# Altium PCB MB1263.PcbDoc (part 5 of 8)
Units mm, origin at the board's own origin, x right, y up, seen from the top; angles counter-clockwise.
Board outline 86 x 120 mm, 6 copper layers (Top Layer, Signal Layer 1, Signal Layer 2, Signal Layer 3, Signal Layer 4, Bottom Layer), stack 1.556 mm thick; 392 components, 421 nets, 1978 pads, 1444 vias.
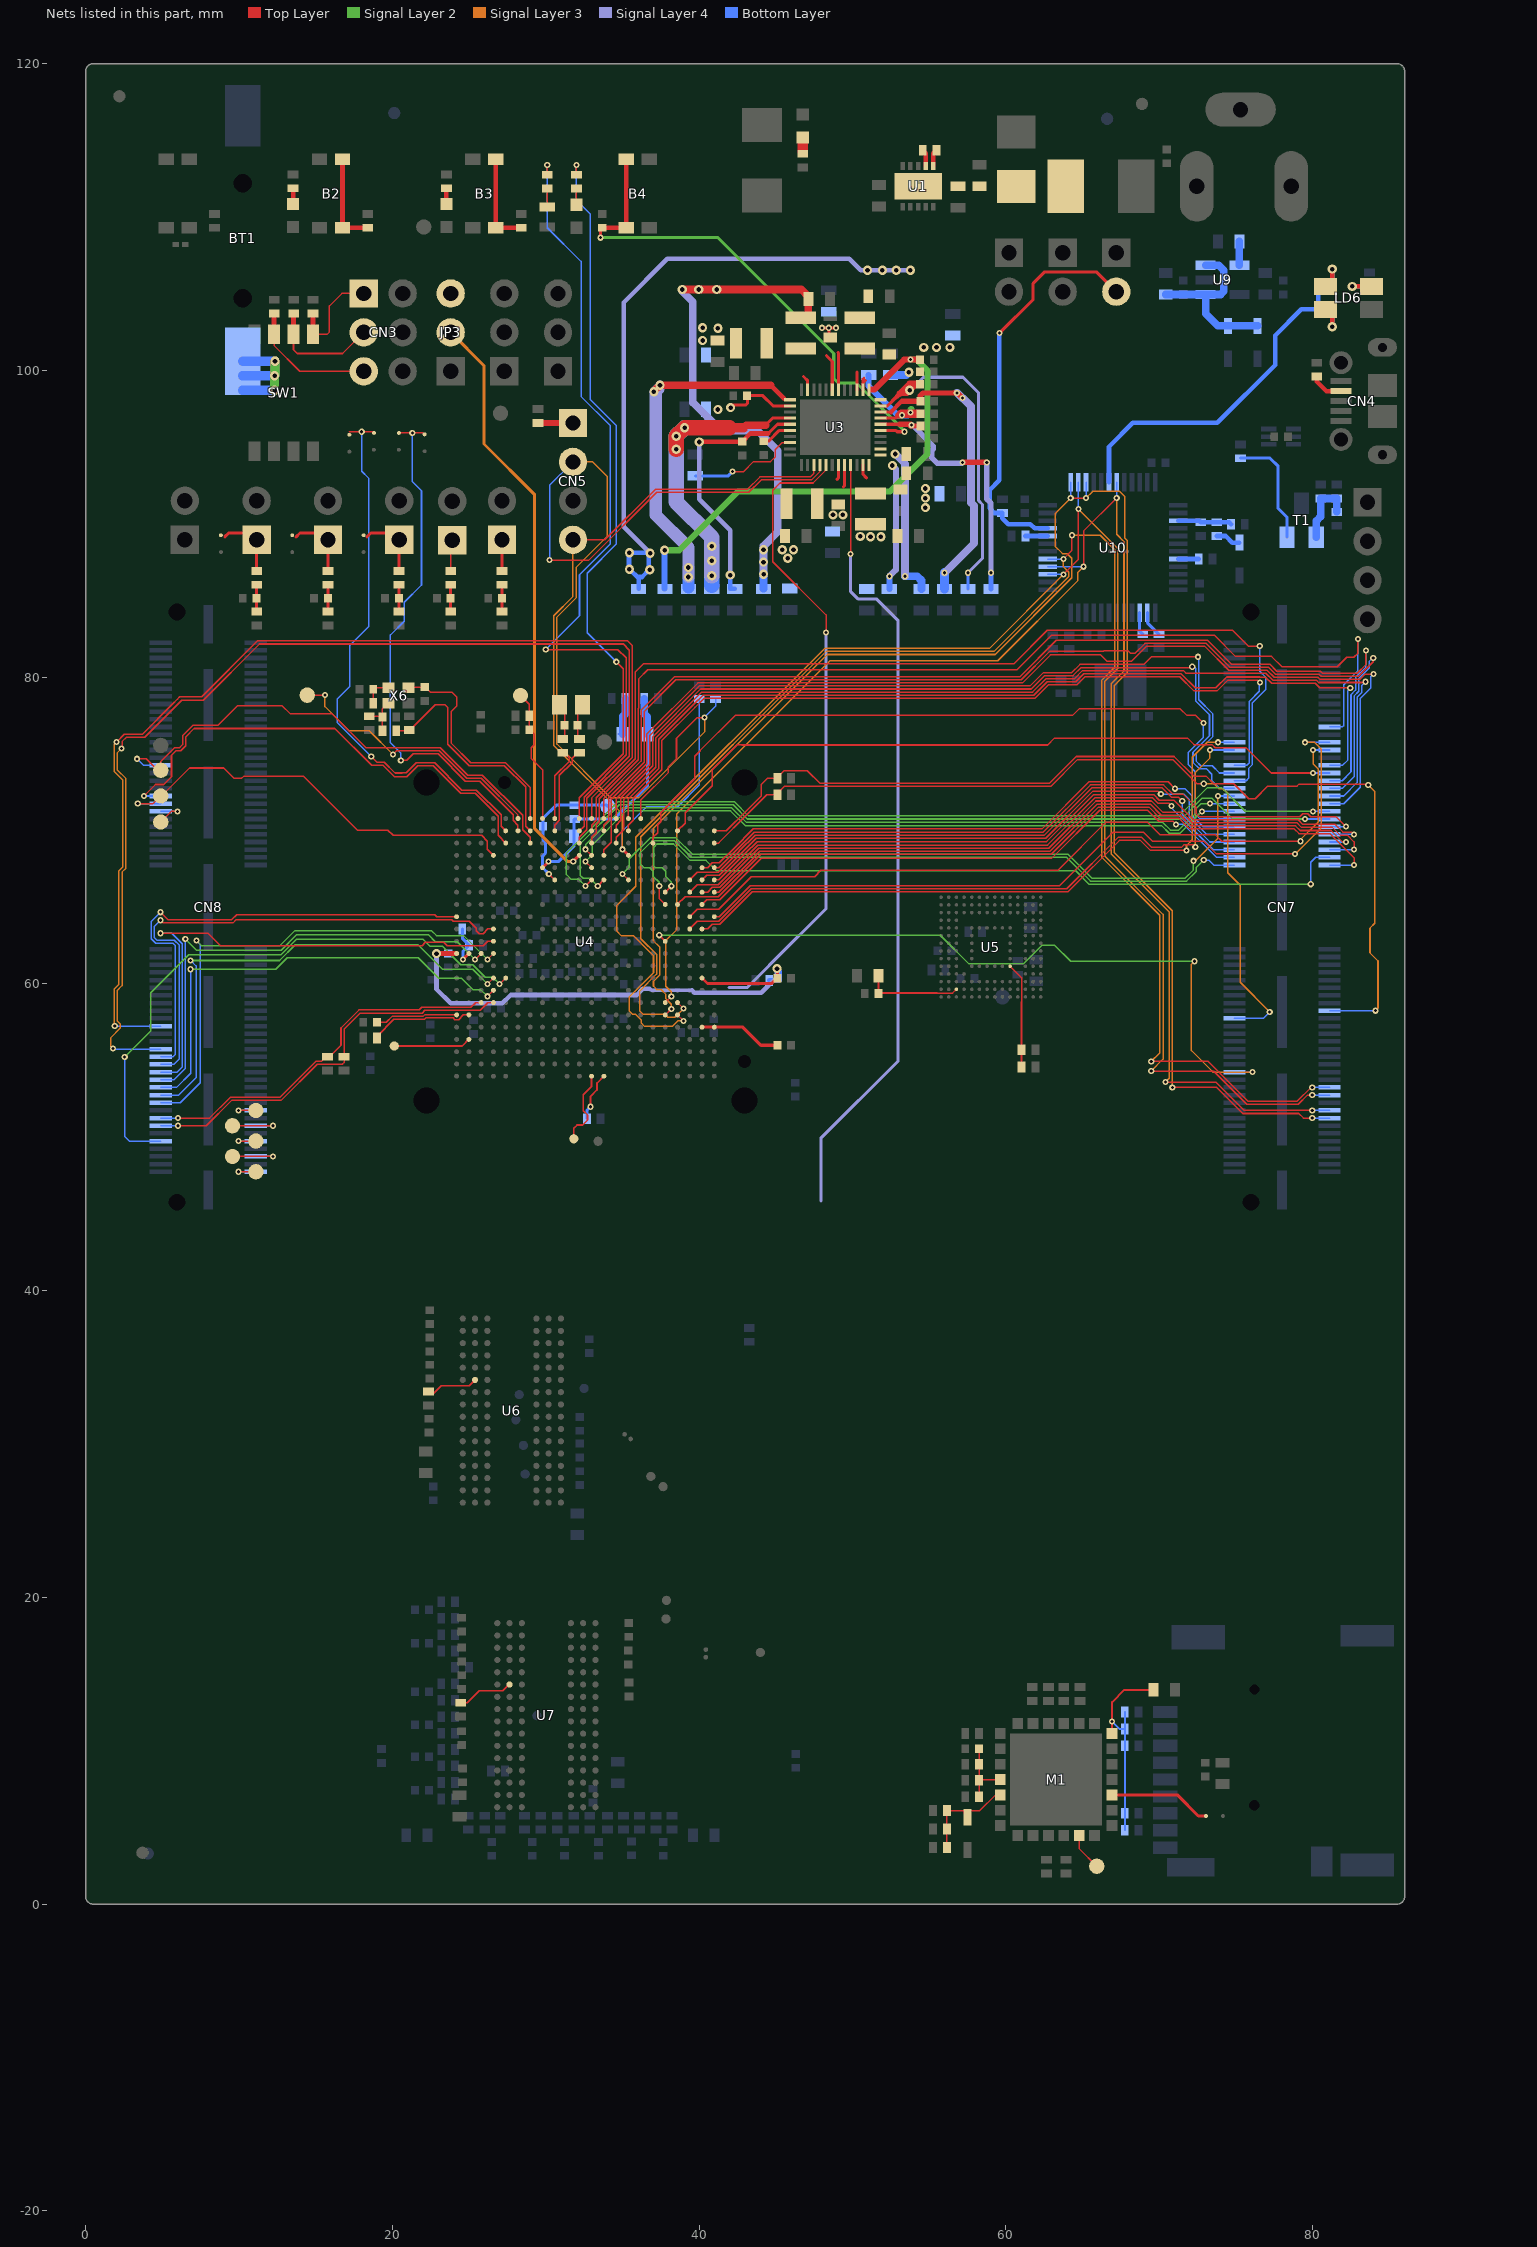
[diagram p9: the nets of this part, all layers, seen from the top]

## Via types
v1: diameter 0.4, hole 0.2, Top Layer to Bottom Layer, tented both sides, 771 vias
v2: diameter 0.6, hole 0.3, Top Layer to Bottom Layer, tented both sides, 670 vias
v3: diameter 0.4, hole 0.2, Top Layer to Bottom Layer, 3 vias

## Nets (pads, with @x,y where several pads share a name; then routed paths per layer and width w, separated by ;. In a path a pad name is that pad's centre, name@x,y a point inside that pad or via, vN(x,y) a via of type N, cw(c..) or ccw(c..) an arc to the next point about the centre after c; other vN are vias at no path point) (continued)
GPIO7: CN8.41 U4.V3 | length 32.1
  Top Layer w0.09: 20.934,73.5 21.646,74.212 22.681,74.212 24.469,72.425 25.396,72.425 26.895,70.926 26.895,69.675 U4.V3@27.39,69.18
  Top Layer w0.1: v1(3.8,72.25) 4.55,73 5.1,73 5.6,73.5 5.6,74.9 5.9,75.2 6.203,75.2 6.525,75.522 6.525,76.1 7.075,76.65 16.25,76.65 18.65,74.25 19.392,74.25 20.142,73.5 20.934,73.5
  Bottom Layer w0.1: v1(3.8,72.25) CN8.41@4.9,72.25
HDMI_CEC: CN7.93 U4.E11 | length 48.8
  Top Layer w0.1: v1@37.4,63.17 U4.E11@37.79,62.78
  Signal Layer 2 w0.1: v1(37.4,63.175) 55.72,63.175 57.595,61.3 61.125,61.3 62.35,62.525 63.175,62.525 64.225,61.475 v1(72.3,61.475)
  Signal Layer 3 w0.1: v1(72.3,61.475) 72.1,61.275 72.1,55.65 73.5,54.25 v1(76.075,54.25)
  Bottom Layer w0.1: CN7.93@74.9,54.25 v1(76.075,54.25)
HSE_IN: C33.2 U4.T1 X6.3 | length 14.9
  Top Layer w0.1: X6.3@21.05,79.3 21.1,79.35 C33.2@22.1,79.35 ; C33.2@22.1,79.3 22.2,79.3 22.5,79 23.9,79 24.2,78.7 24.2,78.125 23.85,77.775 23.85,75.676 25.106,74.42 27.381,74.42 28.99,72.811 U4.T1@28.99,70.78
HSE_OUT: R26.2 R303.1 U4.T2 | length 15.7
  Top Layer w0.09: 23.625,77.875 23.625,75.625 25.025,74.225 27.3,74.225 28.685,72.84 28.685,70.285 U4.T2@28.99,69.98
  Top Layer w0.1: R26.2@20.2,76.5 20.25,76.503 20.255,76.503 R303.1@21.1,76.5 ; R303.1@21.1,76.6 21.2,76.6 22.8,78.2 23.425,78.2 23.625,78 23.625,77.875
I2C2_SCL: CN7.79 R31.1 U4.A3 | length 54.6
  Top Layer w0.1: U4.A3@40.99,69.18 41.263,69.18 41.297,69.214 41.297,69.221 43.131,71.055 43.138,71.055 44.408,72.325 R31.1@45.1,72.325 45.1,72.425 45.55,72.875 62.925,72.875 64.675,74.625 70.886,74.625 72.461,73.05 v1(72.9,73.05)
  Signal Layer 3 w0.09: 74.15,72.725 74.45,72.425 74.45,67.25 75.27,66.43 75.27,65.4
  Signal Layer 3 w0.1: v1(72.9,73.05) 73.575,73.05 73.9,72.725 74.15,72.725 ; 75.275,65.4 75.275,60.1 v1(77.2,58.175)
  Bottom Layer w0.1: CN7.79@74.9,57.75 76.775,57.75 v1(77.2,58.175)
I2C2_SDA: CN7.78 R30.1 U4.A2 | length 65.7
  Top Layer w0.1: U4.A2@40.99,69.98 41.773,69.98 43.048,71.255 43.055,71.255 44.052,72.252 44.052,73.002 44.45,73.4 R30.1@45.1,73.4 45.1,73.475 45.525,73.9 47.05,73.9 47.875,73.075 62.842,73.075 64.592,74.825 70.969,74.825 72.244,73.55 73.05,73.55 73.55,73.05 74.855,73.05 75.83,72.075 76.25,72.075 77.075,72.9 78.98,72.9 79.105,73.025 83.625,73.025 v1(83.625,72.975)
  Signal Layer 3 w0.1: v1(83.625,72.975) 84.05,72.55 84.05,63.951 83.739,63.64 83.739,62.015 84.26,61.494 84.26,58.409 v1(84.104,58.253)
  Bottom Layer w0.1: CN7.78@81.1,58.25 84.101,58.25 v1(84.104,58.253)
I2C4_SCL: CN5.2 R53.2 U3.4 U4.G1 | length 72.8
  Top Layer w0.1: v1(30.251,87.629) 32.812,87.629 37.233,92.05 43.238,92.05 44.044,92.856 47.335,92.856 47.879,93.4 U3.4@47.879,93.836 ; U4.G1@36.19,70.78 36.19,71.982 37.995,73.787 37.995,74.17 38.525,74.7 38.525,76.02 39.855,77.35 40.323,77.35 v1(40.352,77.379)
  Signal Layer 3 w0.1: CN5.2@31.775,94.03 33.07,94.03 34,93.1 34,89.175 31.975,87.15 31.975,85.167 30.725,83.917 30.725,75.633 34.208,72.15 36.075,72.15 40.352,76.427 v1(40.352,77.379)
  Bottom Layer w0.1: v1(30.251,87.629) 30.251,92.506 CN5.2@31.775,94.03 ; v1(40.352,77.379) 41.075,78.102 R53.2@41.075,78.575
I2C4_SDA: CN5.4 R93.2 U3.3 U4.H4 | length 54.2
  Top Layer w0.1: CN5.4@31.775,88.95 33.85,88.95 37.15,92.25 43.155,92.25 43.961,93.056 47.252,93.056 47.479,93.283 U3.3@47.479,93.836
  Top Layer w0.2: v1@35,68.77 U4.H4@35.39,68.38
  Signal Layer 3 w0.1: CN5.4@31.775,88.95 31.775,85.25 30.525,84 30.525,75.55 35,71.075 v1(35,68.775)
  Bottom Layer w0.1: v1(35,68.775) 35,69.975 36.575,71.55 38.6,71.55 40,72.95 R93.2@40,78.575
I2C5_SCL: CN8.105 R34.1 U4.Y16 | length 24.7
  Top Layer w0.09: 21.75,58.3 21.925,58.475 25.116,58.475 25.421,58.78 U4.Y16@25.79,58.78
  Top Layer w0.1: v1(6.025,51.25) 8.084,51.25 9.434,52.6 12.662,52.6 15.017,54.955 15.38,54.955 15.675,55.25 R34.1@15.775,55.25 15.9,55.25 16.65,56 16.65,57.125 17.825,58.3 21.75,58.3
  Bottom Layer w0.1: CN8.105@4.9,51.25 v1(6.025,51.25)
I2C5_SDA: CN8.107 R35.1 U4.W16 | length 26.3
  Top Layer w0.09: 21.937,58.1 22.121,58.285 25.726,58.285 26.221,58.78 U4.W16@26.59,58.78
  Top Layer w0.1: v1(6.025,50.75) 7.867,50.75 9.517,52.4 12.745,52.4 15.1,54.755 16.73,54.755 16.85,54.875 R35.1@16.85,55.25 16.85,57.042 17.908,58.1 21.937,58.1
  Bottom Layer w0.1: CN8.107@4.9,50.75 v1(6.025,50.75)
JTCK_SWCLK: CN7.100 U4.D17 U10.15 U10.26 | length 113.8
  Top Layer w0.1: U4.D17@38.59,57.98 v1@38.98,57.59 ; v1(63.75,86.7) 64.725,87.675 v1(64.725,90.95) ; v1(69.475,54.325) 69.475,54.3 73.549,54.3 75.699,52.15 79.067,52.15 79.667,52.75 v1(79.975,52.75)
  Signal Layer 3 w0.1: v1(38.98,57.585) 38.601,57.585 38.246,57.23 36.445,57.23 36.24,57.435 36.24,57.625 35.835,58.03 35.645,58.03 35.44,58.235 35.44,59.141 37.025,60.726 37.025,61.842 35.737,63.13 34.945,63.13 34.625,63.45 34.625,65.115 35.875,66.365 35.875,69.556 48.194,81.875 58.925,81.875 v1(63.75,86.7) ; v1(64.725,90.95) 64.733,90.95 67.3,88.383 67.3,80.567 66.46,79.727 66.46,68.316 70.25,64.526 70.25,55.1 v1(69.475,54.325)
  Bottom Layer w0.1: U10.15@62.725,86.7 v1(63.75,86.7) ; v1(64.725,90.95) U10.26@64.725,92.7 ; v1(79.975,52.75) CN7.100@81.1,52.75
JTDI: CN7.98 U4.D16 U10.17 | length 106.8
  Top Layer w0.1: U4.D16@38.59,58.78 v1@38.98,58.39 ; v1(63.75,87.7) 64.3,88.25 v1(64.3,89.25) ; v1(69.475,54.95) 73.181,54.95 75.781,52.35 78.984,52.35 79.884,53.25 v1(79.975,53.25)
  Signal Layer 3 w0.1: v1(38.98,58.385) 38.978,58.385 38.413,57.82 37.957,57.82 37.747,58.03 36.32,58.03 36.14,58.21 36.14,59.558 37.225,60.643 37.225,61.925 36.2,62.95 36.2,69.599 48.276,81.675 59.22,81.675 64.1,86.555 64.1,86.845 63.75,87.195 v1(63.75,87.7) ; v1(64.3,89.25) 66.15,89.25 67.1,88.3 67.1,80.65 66.26,79.81 66.26,68.233 70.025,64.469 70.025,55.5 v1(69.475,54.95)
  Bottom Layer w0.1: U10.17@62.725,87.7 v1(63.75,87.7) ; v1(79.975,53.25) CN7.98@81.1,53.25
JTDO_TRACESWO: CN7.104 U4.E16 U10.16 U10.31 | length 106.9
  Top Layer w0.1: U4.E16@37.79,58.78 v1@38.179,59.17 ; v1(65.068,87.2) 65.068,89.518 v1(67.225,91.675) ; v1(70.4,53.6) 73.683,53.6 75.533,51.75 v1(79.975,51.75)
  Signal Layer 3 w0.1: v1(38.185,59.17) 38.185,59.484 37.826,59.843 37.826,62.824 38.55,63.547 38.55,71.1 48.525,81.075 59.468,81.075 64.7,86.307 64.7,86.832 v1(65.068,87.2) ; v1(67.225,91.675) 67.225,89.308 67.7,88.833 67.7,80.401 66.86,79.562 66.86,68.482 70.65,64.692 70.65,53.85 v1(70.4,53.6)
  Bottom Layer w0.1: U10.16@62.725,87.2 v1(65.068,87.2) ; v1(67.225,91.675) U10.31@67.225,92.7 ; v1(79.975,51.75) CN7.104@81.1,51.75
JTMS_SWDIO: CN7.106 U4.E17 U10.25 U10.27 | length 111.1
  Top Layer w0.1: U4.E17@37.79,57.98 v1@38.179,58.37 ; v1(64.225,91.675) v1(65.225,91.675) ; v1(70.85,53.25) 73.75,53.25 75.45,51.55 79.1,51.55 79.4,51.25 v1(79.975,51.25)
  Signal Layer 3 w0.1: v1(38.185,58.37) 38.185,58.675 37.835,59.025 37.835,59.314 37.524,59.625 37.255,59.625 37.025,59.855 37.025,60.16 37.425,60.56 37.425,60.824 37.426,60.825 37.426,62.4 37,62.826 37,70.116 48.359,81.475 59.303,81.475 64.3,86.472 64.3,87.75 64,88.05 63.687,88.05 63.687,88.063 63.225,88.525 63.225,90.675 v1(64.225,91.675) ; v1(65.225,91.675) 65.675,92.125 67.4,92.125 67.75,91.775 67.75,89.075 67.9,88.925 67.9,80.29 67.06,79.45 67.06,68.565 70.85,64.775 v1(70.85,53.25)
  Bottom Layer w0.1: v1(64.225,91.675) U10.25@64.225,92.7 ; v1(65.225,91.675) U10.27@65.225,92.7 ; v1(79.975,51.25) CN7.106@81.1,51.25
LCD_BL_CTRL: CN8.111 U4.V14 | length 38.5
  Top Layer w0.1: v1@27,59.99 U4.V14@27.39,60.38
  Signal Layer 2 w0.1: v1(2.55,55.225) 4.25,56.925 4.25,59.42 6.73,61.9 12.741,61.9 13.766,62.925 21.975,62.925 22.45,62.45 23.265,62.45 24.465,61.25 25.24,61.25 26.05,60.44 26.545,60.44 v1(26.995,59.99)
  Bottom Layer w0.1: v1(2.55,55.225) 2.55,50.05 2.85,49.75 CN8.111@4.9,49.75
LED_B: R5.1 U4.M2 | length 53.7
  Top Layer w0.09: v1(30,81.8) 34.7,81.8 35.25,81.25 35.25,74.938 32.495,72.183 32.495,70.285 U4.M2@32.19,69.98
  Top Layer w0.1: R5.1@30.1,112.75 v1(30.1,113.4)
  Bottom Layer w0.1: v1(30,81.8) 32.2,84 32.2,86.68 34.2,88.68 34.2,96.4 32.3,98.3 32.3,107.1 30.1,109.3 v1(30.1,113.4)
LED_STLINK: R57.2 R58.2 U10.30 | length 22.3
  Bottom Layer w0.3: U10.30@66.725,92.7 66.725,95.025 68.275,96.575 73.775,96.575 77.55,100.35 77.55,102.275 79.25,103.975 R58.2@80.375,103.975 R57.2@80.375,105.475
LED_Y: R6.1 U4.M1 | length 47.3
  Top Layer w0.09: U4.M1@32.19,70.78 32.19,72.146 35.05,75.007 35.05,80.55
  Top Layer w0.1: R6.1@32,112.75 v1(32,113.4) ; v1(34.6,81) 35.05,80.55
  Bottom Layer w0.1: v1(32,113.4) 32,111.1 32.9,110.2 32.9,98.1 34.6,96.4 34.6,88.675 32.7,86.775 32.7,82.9 v1(34.6,81)
LTDC_B0: CN7.57 U4.B8 | length 38.5
  Top Layer w0.09: U4.B8@40.19,65.18 40.495,65.485 41.336,65.485 44.052,68.2
  Top Layer w0.1: 44.052,68.2 63,68.2 66.125,71.325 69.241,71.325 69.967,70.599 70.901,70.599 v1(71.1,70.4)
  Bottom Layer w0.1: v1(71.1,70.4) 71.586,70.4 73.736,68.25 CN7.57@74.9,68.25
LTDC_B1: CN7.54 U4.A7 | length 45.7
  Top Layer w0.09: U4.A7@40.99,65.98 41.294,65.98 43.582,68.267 43.582,68.274 43.957,68.65 46.839,68.65
  Top Layer w0.1: 46.839,68.65 62.88,68.65 65.955,71.725 69.407,71.725 70.133,70.999 71.366,70.999 72.064,70.3 78.889,70.3 79.189,70 81.203,70 81.953,69.25 v1(82.175,69.25)
  Bottom Layer w0.1: CN7.54@81.1,69.25 v1(82.175,69.25)
LTDC_B2: CN7.56 U4.B7 | length 48.2
  Top Layer w0.09: U4.B7@40.19,65.98 40.558,65.98 40.863,66.285 41.33,66.285 43.392,68.346 43.392,68.353 43.889,68.85 46.756,68.85
  Top Layer w0.1: 46.756,68.85 62.797,68.85 65.872,71.925 69.489,71.925 70.216,71.199 71.449,71.199 72.147,70.5 78.972,70.5 79.272,70.2 81.286,70.2 81.786,69.7 82.255,69.7 82.7,69.255 v1(82.7,68.75)
  Bottom Layer w0.1: CN7.56@81.1,68.75 v1(82.7,68.75)
LTDC_B3: CN7.55 U4.C7 | length 39.5
  Top Layer w0.09: U4.C7@39.39,65.98 39.885,66.475 41.252,66.475 43.202,68.425 43.202,68.432 43.82,69.05 46.666,69.05
  Top Layer w0.1: 46.666,69.05 62.714,69.05 65.789,72.125 69.572,72.125 69.922,71.775 70.625,71.775 70.8,71.6 v1(70.803,71.603)
  Signal Layer 2 w0.1: v1@70.8,71.607 v1(70.803,71.603)
  Bottom Layer w0.1: v1(70.803,71.603) 70.803,71.465 73.519,68.75 CN7.55@74.9,68.75
LTDC_B4: CN7.51 U4.B6 | length 38.9
  Top Layer w0.09: U4.B6@40.19,66.78 40.495,67.085 41.324,67.085 42.822,68.582 42.822,68.589 43.732,69.5 46.558,69.5
  Top Layer w0.1: 46.558,69.5 62.599,69.5 65.649,72.55 69.925,72.55 v1(70.1,72.375)
  Bottom Layer w0.1: v1(70.1,72.375) 71.6,72.375 71.95,72.025 71.95,70.884 73.084,69.75 CN7.51@74.9,69.75
LTDC_B5: CN7.52 U4.A6 | length 46.7
  Top Layer w0.09: U4.A6@40.99,66.78 41.288,66.78 43.012,68.503 43.012,68.511 43.776,69.275 46.616,69.275
  Top Layer w0.1: 46.616,69.275 62.656,69.275 65.706,72.325 69.655,72.325 70.005,71.975 70.955,71.975 72.23,70.7 79.055,70.7 79.355,70.4 81.475,70.4 81.975,69.9 82.55,69.9 v1(82.7,69.75)
  Bottom Layer w0.1: CN7.52@81.1,69.75 v1(82.7,69.75)
LTDC_B6: CN7.53 U4.C6 | length 40
  Top Layer w0.09: U4.C6@39.39,66.78 39.885,67.275 41.246,67.275 42.632,68.661 42.632,68.668 43.664,69.7 46.475,69.7
  Top Layer w0.1: 46.475,69.7 62.516,69.7 65.591,72.775 70.201,72.775 70.801,72.175 71.25,72.175 v1(71.5,71.925)
  Bottom Layer w0.1: v1(71.5,71.925) 71.5,71.051 73.301,69.25 CN7.53@74.9,69.25
LTDC_B7: CN7.50 U4.A5 | length 46
  Top Layer w0.09: U4.A5@40.99,67.58 41.282,67.58 42.442,68.74 42.442,68.747 43.595,69.9 46.9,69.9
  Top Layer w0.1: 46.9,69.9 62.433,69.9 65.508,72.975 70.283,72.975 70.883,72.375 71.545,72.375 72.425,71.495 72.425,71.105 72.63,70.9 79.155,70.9 79.355,71.1 79.68,71.1 79.88,70.9 81.525,70.9 v1(82.175,70.25)
  Bottom Layer w0.1: CN7.50@81.1,70.25 v1(82.175,70.25)
LTDC_CLK: CN7.36 U4.D2 | length 47
  Top Layer w0.09: U4.D2@38.59,69.98 39.085,70.475 39.085,71.143 40.845,72.904 40.845,73.943 40.854,73.952 ; 41.45,74.555 41.457,74.555 42.476,75.575 42.775,75.575
  Top Layer w0.1: 40.85,73.956 41.45,74.555 ; 42.775,75.575 62.725,75.575 63.175,76.025 71.836,76.025 72.261,75.6 73.445,75.6 73.645,75.4 75.65,75.4 77.3,73.75 v1(80.025,73.75)
  Bottom Layer w0.1: v1(80.025,73.75) CN7.36@81.1,73.75
LTDC_DE: CN7.49 U4.B5 | length 39
  Top Layer w0.09: U4.B5@40.19,67.58 40.558,67.58 40.863,67.885 41.318,67.885 42.252,68.818 42.252,68.825 43.526,70.1 46.9,70.1
  Top Layer w0.1: 46.9,70.1 62.35,70.1 65.425,73.175 70.578,73.175 v1(71.028,72.725)
  Bottom Layer w0.1: v1(71.028,72.725) 71.675,72.725 72.15,72.25 72.15,70.967 72.867,70.25 CN7.49@74.9,70.25
LTDC_G0: CN7.43 U4.L4 | length 45.6
  Top Layer w0.1: v1@32.6,68.77 U4.L4@32.99,68.38
  Signal Layer 2 w0.1: v1(32.6,68.775) 32.6,69.075 35,71.475 42.134,71.475 43.084,70.525 70.233,70.525 70.733,70.025 71.267,70.025 72.425,71.183 72.425,71.45 72.725,71.75 v1(73.3,71.75)
  Bottom Layer w0.1: v1(73.3,71.75) CN7.43@74.9,71.75
LTDC_G1: CN7.41 U4.H6 | length 47
  Top Layer w0.1: v1@35,67.17 U4.H6@35.39,66.78
  Signal Layer 2 w0.1: v1(35,67.175) 35.45,67.625 35.45,68.16 36.81,69.52 38.496,69.52 39.566,68.45 64.041,68.45 65.591,66.9 71.7,66.9 72.225,67.425 v1(72.225,68.025)
  Signal Layer 3 w0.1: v1(72.225,68.025) 72.355,68.025 73.825,69.495 v1(73.825,72.25)
  Bottom Layer w0.1: v1(73.825,72.25) CN7.41@74.9,72.25
LTDC_G2: CN7.37 U4.L2 | length 64
  Top Layer w0.09: U4.L2@32.99,69.98 32.99,70.348 33.295,70.653 33.295,72.148 35.83,74.684 35.83,78.034 35.833,78.036 35.835,78.038
  Top Layer w0.1: 35.835,78.038 35.835,80.335 36.375,80.875 60.525,80.875 62.7,83.05 74.775,83.05 75.8,82.025 v1(76.55,82.025)
  Bottom Layer w0.1: CN7.37@74.9,73.25 75.675,73.25 75.825,73.4 75.825,74.05 76.075,74.3 76.075,78.325 76.929,79.179 76.929,80.001 76.55,80.38 v1(76.55,82.025)
LTDC_G3: CN7.42 U4.J3 | length 65.6
  Top Layer w0.09: U4.J3@34.59,69.18 34.59,69.548 35.085,70.043 35.085,72.043 37.17,74.129 37.17,76.027
  Top Layer w0.1: 37.175,76.027 40.173,79.025 61.739,79.025 62.614,79.9 64.466,79.9 64.991,80.425 71.575,80.425 71.75,80.25 76.948,80.25 77.408,79.79 80.249,79.79 80.389,79.65 83.4,79.65 v1(83.45,79.7) ; v1(83.45,79.7) 83.575,79.7 v1(83.45,79.7)
  Bottom Layer w0.1: CN7.42@81.1,72.25 82.025,72.25 82.9,73.125 82.9,78.689 83.2,78.989 83.2,79.45 v1(83.45,79.7)
LTDC_G4: CN7.48 U4.K6 | length 55.5
  Top Layer w0.12: v1(33.39,66.38) U4.K6@33.79,66.78
  Signal Layer 2 w0.1: v1(33.39,66.38) 32.89,66.88 32.445,66.88 32.24,67.085 32.24,69.125 34.79,71.675 42.217,71.675 43.142,70.75 71.442,70.75 72.792,72.1 73.445,72.1 74.795,70.75 v1(79.5,70.75)
  Bottom Layer w0.1: v1(79.5,70.75) CN7.48@81.1,70.75
LTDC_G5: CN7.60 U4.D8 | length 50.2
  Top Layer w0.09: U4.D8@38.59,65.18 39.085,65.675 41.258,65.675 43.772,68.189 43.772,68.196 44.026,68.45 45.85,68.45
  Top Layer w0.1: 45.85,68.45 62.963,68.45 66.038,71.525 69.324,71.525 70.05,70.799 71.283,70.799 71.982,70.1 78.807,70.1 79.107,69.8 79.272,69.8 81.12,69.8 82.7,68.22 v1(82.7,67.75)
  Bottom Layer w0.1: CN7.60@81.1,67.75 v1(82.7,67.75)
LTDC_G6: CN7.58 U4.E7 | length 50.6
  Top Layer w0.1: U4.E7@37.79,65.98 v1@38.179,66.37
  Signal Layer 2 w0.1: v1(38.185,66.37) 38.185,66.64 37.825,67 37.825,67.35 37.6,67.575 37.15,67.575 37.035,67.69 37.035,68.914 37.24,69.12 38.33,69.12 39.4,68.05 40.45,68.05 41.125,67.375 64.55,67.375 65.425,66.5 v1(79.875,66.5)
  Bottom Layer w0.1: v1(79.875,66.5) 79.875,67.925 80.2,68.25 CN7.58@81.1,68.25
LTDC_G7: CN7.59 U4.E8 | length 45.3
  Top Layer w0.1: v1(37.4,66.375) 37.4,65.57 U4.E8@37.79,65.18
  Signal Layer 2 w0.1: v1(37.4,66.375) 37.4,66.625 37,67.025 37,67.35 36.775,67.575 36.4,67.575 36.175,67.8 36.175,68.575 36.919,69.32 38.413,69.32 39.483,68.25 63.958,68.25 65.508,66.7 71.783,66.7 72.425,67.342 72.425,67.6 v1(72.9,68.075)
  Bottom Layer w0.1: v1(72.9,68.075) 73.225,68.075 73.55,67.75 CN7.59@74.9,67.75
LTDC_HSYNC: CN7.33 U4.H2 | length 54.9
  Top Layer w0.09: U4.H2@35.39,69.98 35.39,70.348 35.695,70.653 35.695,72.102 37.56,73.967 37.56,75.275
  Top Layer w0.1: 37.56,75.275 37.56,75.57 37.565,75.575 37.565,75.865 39.725,78.025 39.739,78.025 40.339,78.625 61.905,78.625 62.78,79.5 64.633,79.5 65.158,80.025 71.342,80.025 72.267,79.1 73.769,79.1 74.478,79.809 76.424,79.809 v1(76.579,79.654)
  Bottom Layer w0.1: CN7.33@74.9,74.25 75.7,74.25 75.875,74.425 75.875,78.425 76.525,79.075 76.525,79.654 76.525,79.675 76.558,79.675 v1(76.579,79.654)
LTDC_R0: CN7.47 U4.F3 | length 50.8
  Top Layer w0.09: U4.F3@36.99,69.18 36.99,69.548 37.295,69.853 37.295,70.385 37.485,70.575 37.485,71.156 39.705,73.376 39.705,74.855 40.064,75.214
  Top Layer w0.1: 40.064,75.214 42.35,77.5 64.35,77.5 64.775,77.925 71.375,77.925 71.8,77.5 72.375,77.5 v1(72.875,77)
  Bottom Layer w0.1: v1(72.875,77) 72.875,76.083 71.9,75.108 71.9,74.284 72.35,73.834 72.35,71.05 72.65,70.75 CN7.47@74.9,70.75
LTDC_R1: CN7.39 U4.J2 | length 55.1
  Top Layer w0.09: U4.J2@34.59,69.98 34.59,70.348 34.895,70.653 34.895,72.122 36.98,74.207 36.98,76.119
  Top Layer w0.1: 36.985,76.119 40.091,79.225 61.656,79.225 62.531,80.1 64.383,80.1 64.908,80.625 72.1,80.625 v1(72.15,80.675)
  Bottom Layer w0.1: v1(72.15,80.675) 72.2,80.725 72.375,80.55 72.375,78.442 73.275,77.542 73.275,76.183 72.2,75.108 72.2,74.442 72.617,74.025 73.075,74.025 73.425,73.675 73.425,73.255 73.93,72.75 CN7.39@74.9,72.75
LTDC_R2: CN7.46 U4.L6 | length 56.4
  Top Layer w0.12: v1(32.59,66.38) U4.L6@32.99,66.78
  Signal Layer 2 w0.1: v1(32.59,66.38) 32.14,66.83 31.645,66.83 31.35,67.125 31.35,68.518 34.707,71.875 42.3,71.875 43.225,70.95 71.295,70.95 73.145,72.8 74.053,72.8 75.603,71.25 v1(80.025,71.25)
  Bottom Layer w0.1: v1(80.025,71.25) CN7.46@81.1,71.25
LTDC_R3: CN7.44 U4.K4 | length 70.4
  Top Layer w0.09: U4.K4@33.79,68.38 33.79,68.748 34.285,69.243 34.285,72.049 36.6,74.365 36.6,76.305
  Top Layer w0.1: 36.605,76.305 39.925,79.625 61.08,79.625 62.905,81.45 66.18,81.45 66.605,81.025 68.178,81.025 69.153,82 72.975,82 74.525,80.45 77.031,80.45 77.491,79.99 80.332,79.99 80.472,79.85 83.075,79.85 83.425,80.2 v1(83.975,80.2)
  Bottom Layer w0.1: CN7.44@81.1,71.75 82.025,71.75 83.1,72.825 83.1,78.607 83.8,79.307 83.8,80.05 83.95,80.2 v1(83.975,80.2)
LTDC_R4: CN7.35 U4.J1 | length 54.7
  Top Layer w0.09: U4.J1@34.59,70.78 34.59,72.086 36.79,74.286 36.79,76.212
  Top Layer w0.1: 36.795,76.212 40.008,79.425 61.574,79.425 62.449,80.3 64.3,80.3 64.825,80.825 68.995,80.825 69.495,81.325 v1(72.525,81.325)
  Bottom Layer w0.1: v1(72.525,81.325) 72.575,81.275 72.575,78.525 73.475,77.625 73.475,76.1 72.4,75.025 72.4,74.525 72.7,74.225 73.45,74.225 73.925,73.75 CN7.35@74.9,73.75
LTDC_R5: CN7.40 U4.K2 | length 70.1
  Top Layer w0.09: U4.K2@33.79,69.98 33.79,70.348 34.095,70.653 34.095,72.128 36.41,74.443 36.41,77.475
  Top Layer w0.1: 36.415,77.475 36.415,77.765 38.475,79.825 60.997,79.825 62.847,81.675 66.35,81.675 66.4,81.725 67.955,81.725 68.13,81.55 68.42,81.55 69.07,82.2 73.058,82.2 74.608,80.65 77.114,80.65 77.574,80.19 80.414,80.19 80.554,80.05 82.992,80.05 83.95,81.008 v1(83.95,81.25)
  Bottom Layer w0.1: CN7.40@81.1,72.75 81.95,72.75 82.7,73.5 82.7,78.772 83,79.072 83,79.91 83.675,80.585 83.675,81.025 83.925,81.275 v1(83.95,81.25)
LTDC_R6: CN7.38 U4.K1 | length 69.2
  Top Layer w0.1: U4.K1@33.79,70.78 33.79,72.099 36.215,74.524 36.215,77.848 38.392,80.025 60.914,80.025 63.289,82.4 73.141,82.4 74.691,80.85 77.197,80.85 77.657,80.39 80.497,80.39 80.637,80.25 82.909,80.25 83.475,80.816 v1(83.475,81.725)
  Bottom Layer w0.1: CN7.38@81.1,73.25 81.925,73.25 82.5,73.825 82.5,78.855 82.8,79.155 82.8,79.993 83.475,80.668 v1(83.475,81.725)
LTDC_R7: CN7.45 U4.L5 | length 45.8
  Top Layer w0.1: v1@32.6,67.97 U4.L5@32.99,67.58
  Signal Layer 2 w0.1: v1(32.6,67.975) 33.04,68.415 33.04,69.075 35.24,71.275 42.051,71.275 43.001,70.325 70.15,70.325 70.65,69.825 71.35,69.825 v1(72.775,71.25)
  Bottom Layer w0.1: v1(72.775,71.25) CN7.45@74.9,71.25
LTDC_VSYNC: CN7.34 U4.H1 | length 59.9
  Top Layer w0.09: 37.365,74.45 37.365,75.941 39.649,78.225 39.656,78.225 ; 76.525,80.009 76.535,79.999 76.924,79.999 77.328,79.595 80.168,79.595 80.463,79.3 v1(82.45,79.3)
  Top Layer w0.1: U4.H1@35.39,70.78 35.39,72.073 37.365,74.048 37.365,74.45 ; 39.656,78.225 40.256,78.825 61.822,78.825 62.697,79.7 64.549,79.7 65.074,80.225 65.075,80.225 71.425,80.225 72.35,79.3 73.686,79.3 74.395,80.009 76.525,80.009
  Bottom Layer w0.1: CN7.34@81.1,74.25 81.95,74.25 82.3,74.6 82.3,79.125 82.45,79.275 v1(82.45,79.3)
MCO1: CN8.33 TP7.1 U4.T3 | length 34.4
  Top Layer w0.09: 18.7,75.4 23.134,75.4 24.929,73.605 25.872,73.605 28.495,70.982 28.495,70.043 28.99,69.548 U4.T3@28.99,69.18
  Top Layer w0.1: v1(3.35,74.675) 3.95,74.675 TP7.1@4.7,73.925 ; TP7.1@4.9,73.925 4.9,74.5 5.8,75.4 6.12,75.4 6.325,75.605 6.325,76.183 6.992,76.85 8.616,76.85 9.891,78.125 12.825,78.125 13.35,77.6 16.081,77.6 18.281,75.4 18.7,75.4
  Bottom Layer w0.1: v1(3.35,74.675) 3.775,74.25 CN8.33@4.9,74.25
MCO2: CN8.43 TP8.1 U4.W4 | length 28.4
  Top Layer w0.09: 19.45,70.025 19.7,70.025 20.05,69.675 25.826,69.675 26.2,69.301 26.2,68.77 U4.W4@26.59,68.38
  Top Layer w0.1: v1(3.4,71.75) 4.4,71.75 TP8.1@4.9,72.25 4.95,72.25 6.775,74.075 9,74.075 9.675,73.4 10.17,73.4 10.32,73.55 14.192,73.55 17.717,70.025 19.45,70.025
  Bottom Layer w0.1: v1(3.4,71.75) CN8.43@4.9,71.75
NAND_ALE: CN8.101 U4.W12 | length 33.3
  Top Layer w0.1: v1@26.2,61.59 U4.W12@26.59,61.98
  Signal Layer 2 w0.1: v1(7.225,62.825) 7.55,62.5 12.675,62.5 13.625,63.45 22.575,63.45 22.875,63.15 24.634,63.15 v1(26.195,61.59)
  Bottom Layer w0.1: CN8.101@4.9,52.25 6.175,52.25 7.475,53.55 7.475,62.575 v1(7.225,62.825)
NAND_CLE: CN8.89 U4.AB9 | length 31.6
  Top Layer w0.1: v1(4.875,64.675) 5.372,64.178 9.52,64.178 9.85,64.508 22.766,64.508 22.894,64.38 U4.AB9@24.19,64.38
  Bottom Layer w0.1: v1(4.875,64.675) 4.275,64.075 4.275,62.95 4.575,62.65 5.7,62.65 5.85,62.5 5.85,55.4 5.7,55.25 CN8.89@4.9,55.25
NAND_D0: CN8.87 U4.M3 | length 74
  Top Layer w0.09: U4.M3@32.19,69.18 32.19,69.548 32.685,70.043 32.685,72.09 35.44,74.845 35.44,80.41 35.44,81.76 35.04,82.16
  Top Layer w0.1: v1(2.35,75.354) 2.375,75.379 2.375,75.797 2.658,76.08 3.855,76.08 6.274,78.499 7.674,78.499 11.335,82.16 35.04,82.16
  Signal Layer 2 w0.1: v1@2.329,75.375 v1(2.35,75.354)
  Signal Layer 3 w0.1: v1(1.775,55.778) 1.625,55.928 1.625,56.48 2.25,57.105 2.25,57.395 2.075,57.57 2.075,59.592 2.375,59.892 2.375,67.292 2.625,67.542 2.625,73.383 2.075,73.933 2.075,75.079 v1(2.35,75.354)
  Bottom Layer w0.1: v1@1.728,55.778 v1(1.775,55.778) ; v1@1.775,55.75 CN8.87@4.9,55.75
NAND_D1: CN8.81 U4.L1 | length 70.9
  Top Layer w0.1: v1(2.025,75.779) 2.526,76.28 3.705,76.28 5.65,78.225 6,78.575 6,78.582 6.143,78.725 7.575,78.725 11.215,82.365 35.335,82.365 35.635,82.065 35.635,74.764 32.99,72.119 U4.L1@32.99,70.78
  Signal Layer 3 w0.1: v1(1.9,57.25) 1.875,57.25 1.875,59.675 2.175,59.975 2.175,67.375 2.425,67.625 2.425,73.3 1.875,73.85 1.875,75.629 v1(2.025,75.779)
  Bottom Layer w0.1: v1(1.9,57.25) CN8.81@4.9,57.25
NAND_D2: CN7.29 U4.C10 | length 44.2
  Top Layer w0.09: U4.C10@39.39,63.58 39.885,64.075 40.316,64.075 40.863,64.075 ; 40.863,64.075 41.27,64.075 43.395,66.2 44.425,66.2
  Top Layer w0.1: 44.425,66.2 63.967,66.2 67.317,69.55 68.858,69.55 69.508,68.9 71.445,68.9 71.62,69.075 72.2,69.075 v1(72.35,68.925)
  Signal Layer 3 w0.1: v1(72.35,68.925) 72.35,73.775 73.3,74.725 v1(73.3,75.25)
  Bottom Layer w0.1: v1(73.3,75.25) CN7.29@74.9,75.25
NAND_D3: CN7.27 U4.B10 | length 43.6
  Top Layer w0.09: U4.B10@40.19,63.58 40.558,63.58 40.863,63.885 41.349,63.885 43.464,66 44.335,66
  Top Layer w0.1: 44.335,66 64.05,66 67.4,69.35 68.775,69.35 69.425,68.7 v1(71.775,68.7)
  Signal Layer 3 w0.1: v1(71.775,68.7) 71.775,69.025 72.15,69.4 72.15,74.775 73.125,75.75 v1(73.825,75.75)
  Bottom Layer w0.1: v1(73.825,75.75) CN7.27@74.9,75.75
NAND_D4: CN8.91 U4.W10 | length 34.4
  Top Layer w0.09: 23.875,64.18 23.98,64.075 25.025,64.075 25.485,63.615 25.485,63.453 25.663,63.275 25.916,63.275 26.221,63.58 U4.W10@26.59,63.58
  Top Layer w0.1: v1(4.875,64.15) 5.047,63.978 9.603,63.978 9.805,64.18 23.875,64.18
  Bottom Layer w0.1: v1(4.875,64.15) 4.475,63.75 4.475,63.033 4.658,62.85 5.783,62.85 6.1,62.533 6.1,55.1 5.75,54.75 CN8.91@4.9,54.75
NAND_D5: CN8.95 U4.Y12 | length 31.2
  Top Layer w0.1: v1@25.4,61.59 U4.Y12@25.79,61.98
  Signal Layer 2 w0.1: v1(6.5,62.925) 7.225,62.2 12.758,62.2 13.758,63.2 22.35,63.2 22.8,62.75 24.235,62.75 v1(25.395,61.59)
  Bottom Layer w0.1: CN8.95@4.9,53.75 5.758,53.75 6.5,54.492 v1(6.5,62.925)
NAND_D6: CN8.93 U4.W11 | length 33.6
  Top Layer w0.09: 12.175,62.5 21.95,62.5 22.15,62.7 23.35,62.7 23.575,62.475 25.916,62.475 26.221,62.78 U4.W11@26.59,62.78
  Top Layer w0.1: v1(4.875,63.3) 7.975,63.3 8.775,62.5 12.175,62.5
  Bottom Layer w0.1: v1(4.875,63.3) 5.616,63.3 6.3,62.616 6.3,54.575 5.975,54.25 CN8.93@4.9,54.25
NAND_D7: CN8.99 U4.W14 | length 31.9
  Top Layer w0.1: v1@26.2,59.99 U4.W14@26.59,60.38
  Signal Layer 2 w0.1: v1(6.85,61.525) 12.649,61.525 13.674,62.55 21.664,62.55 23.264,60.95 25.235,60.95 v1(26.195,59.99)
  Bottom Layer w0.1: CN8.99@4.9,52.75 6.075,52.75 7.2,53.875 7.2,61.175 v1(6.85,61.525)
NAND_NCE: CN8.97 U4.W15 | length 30.4
  Top Layer w0.1: v1@6.803,60.953 v1(6.85,60.953) ; v1@26.2,59.19 U4.W15@26.59,59.58
  Signal Layer 2 w0.1: v1(6.85,60.953) 12.403,60.953 13.15,61.7 21.692,61.7 23.022,60.37 24.505,60.37 25.245,59.63 25.755,59.63 v1(26.195,59.19)
  Bottom Layer w0.1: CN8.97@4.9,53.25 5.925,53.25 6.85,54.175 v1(6.85,60.953)
NAND_NOE: CN7.30 U4.C9 | length 50.6
  Top Layer w0.09: U4.C9@39.39,64.38 39.885,64.875 40.316,64.875 40.863,64.875 ; 40.863,64.875 41.264,64.875 43.389,67 47.525,67 47.925,67.4
  Top Layer w0.1: 47.925,67.4 63.375,67.4 66.5,70.525 69.25,70.525 70.065,69.71 73.665,69.71 74.075,69.3 v1(79.2,69.3)
  Signal Layer 3 w0.1: v1(79.2,69.3) 79.15,69.35 80.375,70.575 80.375,74 80.025,74.35 v1(80.025,75.25)
  Bottom Layer w0.1: v1(80.025,75.25) CN7.30@81.1,75.25
NAND_NWAIT: CN7.24 U4.L3 | length 69.2
  Top Layer w0.09: U4.L3@32.99,69.18 32.99,69.548 33.295,69.853 33.295,70.385 33.485,70.575 33.485,72.07 36.02,74.605 36.02,77.941
  Top Layer w0.1: 36.025,77.941 36.025,77.946 36.049,77.969 36.049,79.874 36.65,80.475 60.725,80.475 62.975,82.725 73.6,82.725 74.975,81.35 77.325,81.35 78,80.675 81.6,80.675 82.225,81.3 82.686,81.3 82.95,81.564 v1(82.95,82.475)
  Bottom Layer w0.1: CN7.24@81.1,76.75 81.95,76.75 82.025,76.825 82.025,79.501 82.95,80.426 v1(82.95,82.475)
NAND_NWE: CN7.28 U4.A9 | length 51.1
  Top Layer w0.09: U4.A9@40.99,64.38 41.306,64.38 43.326,66.4 46.936,66.4
  Top Layer w0.1: 46.936,66.4 63.5,66.4 67,69.9 68.95,69.9 69.54,69.31 72.9,69.31 73.735,68.475 v1(78.85,68.475)
  Signal Layer 3 w0.1: v1(78.85,68.475) 78.87,68.475 80.575,70.18 80.575,75.3 80.125,75.75 v1(79.5,75.75)
  Bottom Layer w0.1: v1(79.5,75.75) CN7.28@81.1,75.75
NetB2_3: B2.3 B2.4 R9.1 | length 6.1
  Top Layer w0.3: B2.4@16.75,113.75 B2.3@16.75,109.3 R9.1@18.4,109.3
NetB3_3: B3.3 B3.4 R10.1 | length 6.1
  Top Layer w0.3: B3.4@26.75,113.75 B3.3@26.75,109.3 R10.1@28.4,109.3
NetB4_3: B4.3 B4.4 C5.2 U3.17 | length 34.5
  Top Layer w0.2: v1(33.575,108.65) 33.575,109.2 C5.2@33.675,109.3 ; U3.17@51.829,96.086 52.814,96.086 52.9,96 v1(53.4,96) ; v1@53.375,96.075 v1@53.4,96.1
  Top Layer w0.3: C5.2@33.675,109.3 B4.4@35.25,109.3 ; B4.3@35.25,113.75 B4.4@35.25,109.3 ; B4.4@35.35,109.2 B4.4@35.25,109.3
  Signal Layer 2 w0.2: v1(33.575,108.65) 41.225,108.65 48.775,101.1 48.775,99.475 49.075,99.175 50.258,99.175 53.4,96.033 v1(53.4,96)
NetBT1_1: BT1.1 JP3.3 | length 13.9
  Signal Layer 2 w0.6: v2(12.325,98.7) v2(12.325,99.65) 12.35,99.675 v2(12.35,100.6)
  Signal Layer 3 w0.6: v2(12.325,98.7) v2(12.325,99.65) 12.35,99.675 v2(12.35,100.6)
  Signal Layer 4 w0.6: v2(12.325,98.7) v2(12.325,99.65) 12.35,99.675 v2(12.35,100.6)
  Bottom Layer w0.6: BT1.1@10.225,98.7 10.25,98.7 v2(12.325,98.7) v2(12.325,99.65) ; BT1.1@10.225,99.65 10.25,99.65 v2(12.325,99.65) ; BT1.1@10.25,100.6 v2(12.35,100.6) 12.35,99.675 v2(12.325,99.65)
NetC3_2: C3.2 D1.2 F1.2 R7.1 U1.EP
NetC6_2: C6.2 L1.2 R82.1 | length 33.7
  Top Layer w0.5: v2(38.9,105.275) v2(39.975,105.275) v2(41.15,105.275) 46.65,105.275 C6.2@47.1,104.825 ; L1.2@47.1,103.275 47.125,103.3 47.125,103.425 C6.2@47.125,104.65
  Signal Layer 4 w0.5: v2@38.9,105.15 39.575,104.475 39.575,97.908 41.427,96.056 43.819,96.056 45.125,94.75 45.125,89.475 44.2,88.55 v2(44.2,88.3) v2(44.2,87.5) 44.202,87.498 v2(44.202,86.706) ; v2(38.9,105.275) 38.9,105.152 v2@38.902,105.15
  Bottom Layer w0.5: R82.1@44.202,85.756 v2(44.202,86.706)
NetC7_2: C7.2 L2.2 R87.1 | length 43.2
  Signal Layer 4 w0.3: v2@36.775,88.1 35.075,89.8 35.075,104.425 37.925,107.275 49.775,107.275 50.525,106.525 50.95,106.525 50.956,106.531 v2(50.977,106.531) v2(51.952,106.531) v2(52.852,106.531) v2(53.777,106.531)
  Bottom Layer w0.3: 36.025,86.525 36.275,86.525 36.75,87 36.725,87.025 36.725,88.075 36.7,88.1 35.452,88.1 35.425,88.1 35.425,87.075 35.46,87.04 36.052,86.448 R87.1@36.052,85.75
  other v2: 36.777,87.006 35.452,87.031 36.802,88.081 35.452,88.106
NetC8_2: C8.2 L3.1 R59.2
  other v2: 40.225,101.95 41.225,102.75 40.225,102.775
NetC9_2: C9.2 R50.2 U3.28 | length 3.9
  Top Layer w0.2: v1(48,102.775) v1@48.425,102.775 ; v1(48.45,102.775) 48.475,102.75 C9.2@48.475,102.25 ; v1@48.45,102.8 48.462,102.788 48.475,102.775 v1(48.925,102.775) ; 49.05,101.175 49.079,101.146 U3.28@49.079,98.736
NetC10_2: C10.2 R60.2 U3.24 | length 1.5
  Top Layer w0.2: 50.754,99.504 50.725,99.475 50.675,99.425 50.675,98.74 U3.24@50.679,98.736 50.679,99.179 50.85,99.35
  other v2: 54.65,101.5 55.475,101.5 56.35,101.5
NetC11_2: C11.2 R86.1 U3.23 | length 33.1
  Top Layer w0.4: 51.2,98.75 51.425,98.75 53.375,100.7 v1(53.775,100.7) C11.2@54.4,100.7
  Signal Layer 2 w0.4: v2(37.75,88.275) 38.7,88.275 42.525,92.1 52.425,92.1 54.9,94.575 54.9,99.975 54.175,100.7 v1(53.775,100.7)
  Bottom Layer w0.3: R86.1@37.75,85.783 R86.1@37.777,85.756
  Bottom Layer w0.4: R86.1@37.75,85.783 v2(37.75,88.275)
NetC13_2: C13.2 R76.1 U3.21 | length 23.7
  Top Layer w0.2: U3.21@51.829,97.686 52.286,97.686 52.65,98.05
  Top Layer w0.25: 52.65,98.05 52.875,98.275
  Top Layer w0.3: 52.875,98.275 53.075,98.475 v2@53.55,98.475 ; v2(53.725,98.7) 54,98.975 ; v2@53.825,98.75 53.75,98.675 v2@53.55,98.475 ; 54.1,99 53.763,98.663 53.575,98.475 v2@53.55,98.475
  Top Layer w0.4: 53.075,98.475 53.512,98.912 53.725,99.125 C13.2@54.4,99.125
  Signal Layer 4 w0.2: v2(53.725,98.7) 53.775,98.7 54.625,99.55 57.2,99.55 58.225,98.525 58.225,91.506 58.475,91.256 58.475,87.75 57.529,86.804 v1@57.525,86.8
  Bottom Layer w0.2: R76.1@57.527,85.756 v1(57.527,86.806)
NetC14_2: C14.2 R63.2 U3.36 | length 4.8
  Top Layer w0.2: v2(42.05,97.575) 42.225,97.75 43.05,97.75 43.15,97.85 43.15,98.356 43.15,98.375 44.125,98.375 44.814,97.686 U3.36@45.929,97.686
  other v2: 41.225,97.45
NetC15_2: C15.2 R77.1 U3.20 | length 20.3
  Top Layer w0.2: U3.20@51.829,97.286 52.507,97.286
  Top Layer w0.3: 52.507,97.286 53.227,98.006
  Top Layer w0.35: 53.25,97.975 C15.2@54.425,97.975 54.425,98.35 54.6,98.525 v1(56.8,98.525) 56.85,98.525 v1(57.175,98.2)
  Signal Layer 4 w0.5: v1@56,86.8 56.004,86.804 57.925,88.725 57.925,91.169 57.725,91.369 57.725,97.65 v1(57.175,98.2) 57.15,98.2 56.813,98.538 v1@56.8,98.55
  Bottom Layer w0.6: R77.1@56.002,85.756 v1(56.002,86.806)
NetC16_2: C16.2 R62.2 U3.19 | length 8.8
  Top Layer w0.2: U3.19@51.829,96.886 52.786,96.886 52.956,97.056 53,97.1
  Top Layer w0.4: v1@53.225,97.233 v1@53.225,97.1 ; v1(53.775,97.25) 53.225,97.25 53.15,97.25 53.1,97.2 52.956,97.056 53.225,97.056 v1(53.225,97.075) v1@53.225,97.1 ; C16.2@54.225,97.1 53.775,97.1 v1@53.225,97.1
  Top Layer w0.5: v1@53.771,97.2 53.775,97.2 C16.2@54.375,97.2
  Signal Layer 2 w0.4: v1(53.775,97.25) 53.775,97.429 53.827,97.481
  Bottom Layer w0.4: R62.2@51.05,99.7 51.05,98.975 52.95,97.075 v1(53.225,97.075) 53.6,97.075 v1(53.775,97.25)
NetC17_2: C17.2 R75.1 U3.18 | length 17.6
  Top Layer w0.2: U3.18@51.829,96.486 53.085,96.486
  Top Layer w0.35: 53.085,96.486 53.789,96.486 v1(53.85,96.425) ; v1@53.775,96.375 53.8,96.375 v1(53.85,96.425) ; C17.2@54.425,96.375 53.9,96.375 v1(53.85,96.425) ; v1(57.175,94) v1(58.75,94)
  Signal Layer 4 w0.35: v1(53.85,96.425) 53.908,96.425 55.283,95.05 55.283,94.871 55.175,94.763 55.175,94.287 55.512,93.95 57.125,93.95 v1(57.175,94) ; v1(58.75,94) 58.75,93.975 58.75,91.625 59.025,91.35 59.025,86.808 v1(59.027,86.806)
  Bottom Layer w0.35: R75.1@59.027,85.756 v1(59.027,86.806)
NetC20_1: C20.1 U3.40 | length 2
  Top Layer w0.2: C20.1@44.202,95.381 44.527,95.381 45.232,96.086 U3.40@45.929,96.086
NetC21_2: C21.2 R83.1 U3.39 | length 17.1
  Top Layer w0.2: 44.507,95.886 45.107,96.486 U3.39@45.929,96.486
  Top Layer w0.3: v2(40.002,95.331) 40.027,95.356 C21.2@42.802,95.356 43.332,95.886 44.507,95.886
  Signal Layer 4 w0.3: v2(40.002,95.331) 40.002,91.598 42.025,89.575 v2(42.025,86.65)
  Bottom Layer w0.3: v2(42.025,86.65) 42.025,85.756 R83.1@42.327,85.756
NetC22_2: C22.2 R78.1 U3.14 | length 10.1
  Signal Layer 4 w0.2: v2(52.775,94.55) v2@52.775,94.625
  Signal Layer 4 w0.5: v2(52.775,94.55) 53.425,93.9 v1(53.425,86.575)
  Bottom Layer w0.5: v1(53.425,86.575) 54.225,86.575 54.5,86.3 R78.1@54.5,85.75
NetC23_2: C23.2 R79.2 U3.13 | length 8.3
  Signal Layer 4 w0.4: v1(52.4,86.575) 52.825,87 52.825,93.575 v2(52.6,93.8)
  Bottom Layer w0.4: R79.2@52.4,85.75 v1(52.4,86.575)
NetC24_2: C24.2 R68.2 U3.12
  other v2: 54.75,91.05 54.75,91.675 54.75,92.3
NetC25_2: C25.2 R72.2 U3.8 | length 1.5
  Top Layer w0.2: 49.4,92.4 49.479,92.479 U3.8@49.479,93.836
  other v2: 48.725,90.575 49.375,90.575
NetC26_2: C26.2 L4.2 R80.1
  other v2: 51.175,89.15 51.85,89.15 50.5,89.175
NetC27_2: C27.2 L5.2 R81.1
  other v2: 45.775,87.75 45.425,88.3 46.15,88.3
NetC28_2: C28.2 R16.1 R21.2 | length 1.8
  Top Layer w0.2: R21.2@11.15,84.275 C28.2@11.15,85.15 R16.1@11.15,86.025
NetC29_2: C29.2 R17.1 R22.2 | length 1.8
  Top Layer w0.2: R22.2@15.8,84.275 C29.2@15.8,85.15 R17.1@15.8,86.025
NetC30_2: C30.2 R18.1 R23.2 | length 1.8
  Top Layer w0.2: R23.2@20.425,84.275 C30.2@20.425,85.15 R18.1@20.425,86.025
NetC31_2: C31.2 R19.1 R24.2 | length 1.8
  Top Layer w0.2: R24.2@23.8,84.27 C31.2@23.8,85.145 R19.1@23.8,86.02
NetC32_2: C32.2 R20.1 R25.2 | length 1.8
  Top Layer w0.2: R25.2@27.15,84.27 C32.2@27.15,85.145 R20.1@27.15,86.02
NetC35_2: C35.2 R26.1 R302.2 X6.1 | length 2.5
  Top Layer w0.1: R302.2@18.5,77.45 19.25,77.45 19.325,77.375 19.4,77.3 19.35,77.25 R26.1@19.35,76.5 ; C35.2@19.35,77.4 19.35,77.95 X6.1@19.5,78.1
NetC36_1: C36.1 R28.2 X2.1 | length 2.4
  Top Layer w0.1: X2.1@30.9,78.2 31.225,77.875 C36.1@31.225,76.85 31.225,76.1 R28.2@31.1,75.975
NetC37_2: C37.2 R29.2 X2.2 | length 2.4
  Top Layer w0.1: R29.2@32.2,75.975 32.075,76.1 C37.2@32.075,76.85 32.075,77.875 X2.2@32.4,78.2
NetC38_2: C38.2 R27.1 TP4.1 U4.R1 | length 8.8
  Top Layer w0.1: TP4.1@28.35,78.8 28.925,78.225 R27.1@28.925,77.475 C38.2@28.925,76.575 29.245,76.255 29.245,75.589 29.053,75.397 29.053,74.692 29.119,74.625 29.79,73.955 U4.R1@29.79,70.78
NetC39_1: C39.1 C41.2 U5.C2 | length 6.3
  Top Layer w0.09: 55.5,59.4 56.382,59.4
  Top Layer w0.1: 56.382,59.4 56.525,59.4 U5.C2@56.775,59.65
  Top Layer w0.13: C39.1@51.7,60.525 C41.2@51.7,59.375 51.725,59.4 55.5,59.4
NetC40_2: C40.2 C93.2 R101.2 U4.AB12 U4.B14 | length 35.9
  Top Layer w0.2: U4.B14@40.19,60.38 40.55,60.02 44.745,60.02 C40.2@45.1,60.375 45.1,60.975 v2(45.075,61)
  Top Layer w0.3: v2(22.875,61.975) 22.88,61.98 U4.AB12@24.19,61.98
  Signal Layer 4 w0.2: 36.761,59.675 36.852,59.585 39.529,59.585 39.534,59.58
  Signal Layer 4 w0.3: v2@22.95,62.05 v2(22.875,61.975) 22.875,59.65 23.795,58.73 27.171,58.73 27.716,59.275 35.925,59.275 36.325,59.675 36.761,59.675 ; 39.534,59.58 39.689,59.425 44.05,59.425 45.075,60.45 v2(45.075,61)
  Bottom Layer w0.3: v2(22.875,61.975) 22.88,61.98 C93.2@23.65,61.98 ; R101.2@44.575,60.225 45.25,60.225 45.25,60.825 v2(45.075,61)
NetC42_1: C42.1 U4.AB17 | length 5.4
  Top Layer w0.1: C42.1@19,57.5 19.6,57.5 20,57.9 22.019,57.9 22.099,57.98 U4.AB17@24.19,57.98
NetC43_2: C43.2 U4.A18 U4.B18 | length 5.4
  Top Layer w0.2: U4.B18@40.19,57.18 U4.A18@40.99,57.18 42.845,57.18 44.025,56 C43.2@45.1,56
NetC55_2: C55.2 M1.20 R111.2 R113.2 R115.2 R121.2 R135.2 | length 13.8
  Top Layer w0.13: M1.20@66.925,11.125 v3(66.925,11.9) 66.925,13.175 67.725,13.975 C55.2@69.625,13.975
  Bottom Layer w0.13: v3(66.925,11.9) 67.4,11.425 R113.2@67.75,11.425 ; R135.2@67.75,4.825 R121.2@67.75,5.925 R115.2@67.75,10.325 R113.2@67.75,11.425 ; R111.2@67.75,12.525 R113.2@67.75,11.425
NetC56_1: C56.1 M1.4 R42.2 R43.1 R44.2 | length 4.5
  Top Layer w0.1: R44.2@58.25,7 R43.1@58.25,8.075 ; C56.1@58.25,10.125 R42.2@58.25,9.125 R43.1@58.25,8.075 ; M1.4@59.625,8.125 58.3,8.125 R43.1@58.25,8.075
NetC60_2: C60.2 U9.4 | length 1.6
  Bottom Layer w0.5: U9.4@75.225,106.85 C60.2@75.225,108.4
NetC62_1: C62.1 C64.2 D3.2 D4.2 U9.1 U9.3 | length 11.5
  Bottom Layer w0.5: C62.1@70.425,104.95 C64.2@71.575,104.95 U9.1@73.025,104.95 ; U9.3@73.025,106.85 73.875,106.85 74.2,106.525 74.2,105.15 74,104.95 U9.1@73.025,104.95 ; D3.2@76.4,102.9 D4.2@74.475,102.9 73.825,102.9 73.025,103.7 U9.1@73.025,104.95
NetC67_2: C67.2 R61.2 U3.22 | length 1.3
  Bottom Layer w0.5: R61.2@52.475,99.7 53.5,99.7 v2(53.675,99.875)
NetC75_2: C75.2 R96.2 TP30.1 U4.P6 | length 9.1
  Top Layer w0.1: v1@30.2,67.17 U4.P6@30.59,66.78
  Bottom Layer w0.2: v1(30.2,67.175) 29.785,67.59 29.785,68.321 29.985,68.521 29.985,69.215 29.825,69.375 C75.2@29.825,70.275 29.825,70.8 30.675,71.65 R96.2@31.885,71.65 33.975,71.65 TP30.1@34.05,71.575
NetC76_2: C76.2 LE1.2 R94.2 R96.1 U4.R5 | length 15.8
  Top Layer w0.2: U4.R5@29.79,67.58 v1@30.18,67.97
  Bottom Layer w0.2: v1(30.185,67.97) 30.82,67.97 31.85,69 C76.2@31.85,69.625 31.85,70.715 R96.1@31.885,70.75 34.475,70.75 36.625,72.9 LE1.2@36.625,76.275
  Bottom Layer w0.5: R94.2@36.425,78.6 36.425,77.625 36.625,77.425 LE1.2@36.625,76.275
NetC300_2: C300.2 R300.2 X6.4 | length 1.9
  Top Layer w0.1: R300.2@18.7,78.3 18.725,78.325 18.75,78.35 C300.2@18.75,79.2 ; C300.2@18.8,79.2 18.9,79.3 X6.4@19.75,79.3
NetCN3_1: CN3.1 R13.2 SW1.1 | length 6.8
  Top Layer w0.1: SW1.1@14.825,102.345 15.745,102.345 15.9,102.5 15.9,104.2 16.715,105.015 CN3.1@18.13,105.015
  Top Layer w0.3: SW1.1@14.825,102.345 R13.2@14.825,103.7
NetCN3_3: CN3.3 R12.2 SW1.2 | length 7.6
  Top Layer w0.1: SW1.2@13.555,102.345 13.555,101.345 13.8,101.1 16.755,101.1 CN3.3@18.13,102.475
  Top Layer w0.3: SW1.2@13.555,102.345 13.555,103.68 R12.2@13.575,103.7
NetCN3_5: CN3.5 R11.2 SW1.3 | length 8.6
  Top Layer w0.1: SW1.3@12.285,102.345 12.285,101.615 13.965,99.935 CN3.5@18.13,99.935
  Top Layer w0.3: SW1.3@12.285,102.345 12.285,103.685 R11.2@12.3,103.7
NetCN4_4: CN4.4 R14.2 | length 2.2
  Top Layer w0.3: R14.2@80.275,99.6 80.275,99.275 80.9,98.65 CN4.4@81.85,98.65
NetCN5_1: CN5.1 R15.1 | length 2.3
  Top Layer w0.4: R15.1@29.5,96.575 31.77,96.575 CN5.1@31.775,96.57
NetCN8_45: CN8.45 TP9.1 | length 2.5
  Top Layer w0.1: TP9.1@4.9,70.55 5.6,71.25 v1(6,71.25)
  Bottom Layer w0.1: CN8.45@4.9,71.25 v1(6,71.25)
NetCN8_104: CN8.104 TP13.1 | length 2.2
  Top Layer w0.1: v1(9.975,51.75) TP13.1@11.1,51.75
  Bottom Layer w0.1: v1(9.975,51.75) CN8.104@11.1,51.75
NetCN8_108: CN8.108 TP14.1 | length 3.8
  Top Layer w0.1: TP14.1@9.575,50.75 v1(12.225,50.75)
  Bottom Layer w0.1: CN8.108@11.1,50.75 v1(12.225,50.75)
NetCN8_112: CN8.112 TP15.1 | length 2.2
  Top Layer w0.1: v1(9.975,49.75) TP15.1@11.1,49.75
  Bottom Layer w0.1: v1(9.975,49.75) CN8.112@11.1,49.75
NetCN8_116: CN8.116 TP18.1 | length 3.8
  Top Layer w0.1: TP18.1@9.575,48.75 v1(12.225,48.75)
  Bottom Layer w0.1: CN8.116@11.1,48.75 v1(12.225,48.75)
NetCN8_120: CN8.120 TP19.1 | length 2.2
  Top Layer w0.1: v1(9.975,47.75) TP19.1@11.1,47.75
  Bottom Layer w0.1: v1(9.975,47.75) CN8.120@11.1,47.75
NetD2_1: D2.1 M1.5 R45.2 R46.1 R47.2 | length 6.4
  Top Layer w0.1: R45.2@56.1,6 56.15,5.95 R46.1@56.15,4.9 ; R47.2@56.15,3.7 56.15,4.85 56.175,4.875 R46.1@56.2,4.9 ; R45.2@56.15,6.1 57.3,6.1 D2.1@57.3,5.9 ; D2.1@57.6,5.8 57.6,6.1 58.3,6.1 59.325,7.125 M1.5@59.625,7.125
NetD5_2: D5.2 R70.1 | length 1.7
  Bottom Layer w0.3: R70.1@73.75,89.2 74.325,89.2 74.755,88.77 D5.2@75.225,88.77
NetJP2_2: JP2.2 R66.2 U10.21 | length 26.6
  Top Layer w0.2: v1(59.575,102.425) 61.775,104.625 61.775,105.675 62.5,106.4 65.93,106.4 JP2.2@67.2,105.13
  Bottom Layer w0.3: v1(59.575,102.425) 59.575,92.825 58.95,92.2 58.95,91 59.25,90.7 R66.2@59.775,90.7 59.775,90.35 60.15,89.975 61.6,89.975 61.875,89.7 U10.21@62.725,89.7
NetJP3_2: JP3.2 U4.M4 | length 38.6
  Top Layer w0.2: v1@31.8,67.99 U4.M4@32.19,68.38
  Signal Layer 3 w0.2: JP3.2@23.8,102.475 25.975,100.3 25.975,95.2 29.275,91.9 29.275,70.125 31.41,67.99 v1(31.795,67.99)
NetJP7_1: JP7.1 R16.2 SB5.1 | length 4.4
  Top Layer w0.2: 9.075,89.15 9.325,89.4 10.705,89.4 JP7.1@11.15,88.955 R16.2@11.15,86.925
NetJP8_1: JP8.1 R17.2 SB6.1 | length 4.4
  Top Layer w0.2: 13.725,89.15 13.975,89.4 15.355,89.4 JP8.1@15.8,88.955 R17.2@15.8,86.925
NetJP9_1: JP9.1 R18.2 SB7.1 | length 4.4
  Top Layer w0.2: 18.35,89.15 18.6,89.4 19.98,89.4 20.425,88.955 R18.2@20.425,86.925
NetJP10_1: JP10.1 R20.2 | length 2.7
  Top Layer w0.2: JP10.1@26.705,89.395 JP10.1@27.15,88.95 R20.2@27.15,86.92
NetJP11_1: JP11.1 R19.2 | length 2.1
  Top Layer w0.1: R19.2@23.8,86.92 23.8,88.83 JP11.1@23.9,88.93
NetL1_1: L1.1 U3.29 | length 2.4
  Top Layer w0.2: 48.302,100.956 48.679,100.579 U3.29@48.679,98.736
NetL2_1: L2.1 U3.25 | length 1.1
  Top Layer w0.2: U3.25@50.279,98.736 50.279,99.883
NetL3_2: L3.2 U3.33 | length 1
  Top Layer w0.2: 46.8,99.6 47.079,99.321 U3.33@47.079,98.736
NetL4_1: L4.1 U3.11 | length 0.9
  Top Layer w0.2: U3.11@50.679,93.836 50.679,93.221 50.9,93
NetL5_1: L5.1 U3.7 | length 1
  Top Layer w0.2: 49,92.9 49.079,92.979 U3.7@49.079,93.836
NetLD1_1: LD1.1 R2.1 | length 0.8
  Top Layer w0.7: R2.1@46.75,114.325 LD1.1@46.75,115.175
NetLD2_1: LD2.1 R3.2 | length 1
  Top Layer w0.3: LD2.1@13.525,110.85 R3.2@13.525,111.875
NetLD3_1: LD3.1 R4.1 | length 1
  Top Layer w0.3: LD3.1@23.525,110.85 R4.1@23.525,111.875
NetLD4_1: LD4.1 R6.2 | length 1.1
  Top Layer w0.1: LD4.1@32,110.8 R6.2@32,111.85
NetLD5_1: LD5.1 R5.2 | length 1.2
  Top Layer w0.1: LD5.1@30.1,110.65 R5.2@30.1,111.85
NetLD6_2: LD6.2 R58.1 | length 2.4
  Top Layer w0.3: LD6.2@80.825,103.975 81.275,103.525 v2(81.275,102.85)
  Bottom Layer w0.3: v2(81.275,102.85) R58.1@81.275,103.975
NetLD6_3: LD6.3 R57.1 | length 2.4
  Top Layer w0.3: LD6.3@80.825,105.475 81.275,105.925 v2(81.275,106.6)
  Bottom Layer w0.3: R57.1@81.275,105.475 v2(81.275,106.6)
NetLD6_4: LD6.4 R56.2 | length 2.4
  Top Layer w0.3: v2(82.575,105.475) LD6.4@83.825,105.475
  Bottom Layer w0.3: v2(82.575,105.475) R56.2@83.7,105.475
NetLE1_1: LE1.1 R95.2 | length 2.6
  Bottom Layer w0.1: LE1.1@34.725,76.275 LE1.1@34.875,76.425
  Bottom Layer w0.5: LE1.1@35.025,76.275 35.025,77.45 35.2,77.625 R95.2@35.2,78.6
NetLNK1_1: LNK1.1 U3.5 | length 41.5
  Top Layer w0.1: v1(48.275,82.9) 48.275,84.05 44.8,87.525 44.8,92.181 45.275,92.656 47.427,92.656 48.279,93.508 U3.5@48.279,93.836
  Signal Layer 4 w0.2: LNK1.1@41.95,59.775 LNK1.1@42.05,59.775 43.15,59.775 44.575,61.2 44.575,61.207 44.868,61.5 44.875,61.5 48.275,64.9 v1(48.275,82.9)
NetLNK2_1: LNK2.1 U3.9 | length 52.1
  Top Layer w0.1: v1(49.879,88.025) U3.9@49.879,93.836
  Signal Layer 4 w0.2: LNK2.1@47.934,45.834 47.934,49.934 52.975,54.975 52.975,83.675 51.55,85.1 50.35,85.1 49.879,85.571 v1(49.879,88.025)
NetM1_12: M1.12 TP29.1 | length 2.5
  Top Layer w0.1: M1.12@64.775,4.475 64.775,3.625 TP29.1@65.925,2.475
NetM1_16: M1.16 SB9.1 | length 6.7
  Top Layer w0.2: M1.16@66.925,7.125 71.175,7.125 72.55,5.75 SB9.1@73.05,5.75
NetR1_1: R1.1 U1.7 | length 1.1
  Top Layer w0.3: R1.1@54.575,114.35 54.775,114.15 U1.7@54.775,113.325
NetR1_2: R1.2 U1.6 | length 1.1
  Top Layer w0.3: U1.6@55.275,113.325 55.275,114.15 R1.2@55.475,114.35
NetR28_1: R28.1 U4.P1 | length 5.1
  Top Layer w0.1: U4.P1@30.59,70.78 30.59,73.566 31.53,74.506 31.53,74.745 31.3,74.975 31.3,74.875 R28.1@31.1,75.075
NetR29_1: R29.1 U4.P2 | length 5.8
  Top Layer w0.09: U4.P2@30.59,69.98 30.59,70.348 30.895,70.653 30.895,73.595 31.725,74.425 31.725,74.725 32.075,75.075 R29.1@32.2,75.075
NetR32_2: R32.2 U4.AA17 | length 6.8
  Top Layer w0.09: R32.2@19,56.475 19,56.6 20.1,57.7 20.45,57.7 ; 23.8,57.78 23.958,57.78 24.063,57.675 24.316,57.675 24.621,57.98 U4.AA17@24.99,57.98
  Top Layer w0.1: 20.45,57.7 22.102,57.7 22.182,57.78 23.8,57.78
NetR33_1: R33.1 R54.2 U5.K5 | length 6.9
  Top Layer w0.09: 61.025,58.825 61.025,60.257
  Top Layer w0.1: U5.K5@60.275,61.15 61.025,60.4 61.025,60.257
  Top Layer w0.13: R54.2@61.025,54.575 R33.1@61.025,55.7 61.025,58.825
NetR36_2: R36.2 U6.L8 | length 3.4
  Top Layer w0.12: R36.2@22.315,33.28 22.36,33.28 22.665,33.28 23.19,33.805 25.015,33.805 U6.L8@25.39,34.18
NetR51_2: R51.2 T1.2 | length 7.5
  Bottom Layer w0.2: R51.2@75.3,94.275 77.225,94.275 77.75,93.75 77.75,91 78.325,90.425 T1.2@78.325,89.125
NetR52_1: R52.1 R65.1 R67.1 T1.1 | length 4.6
  Bottom Layer w0.5: T1.1@80.225,89.125 80.225,90.175 80.525,90.475 R65.1@80.525,91.65 R52.1@81.575,91.65 R67.1@81.575,90.775
NetR55_2: R55.2 U7.L8 | length 3.6
  Top Layer w0.12: R55.2@24.45,13.13 24.88,13.13 25.66,13.91 27.2,13.91 U7.L8@27.6,14.31
NetR64_2: R64.2 U3.42 | length 7.4
  Top Layer w0.1: v1(42.175,93.4) 42.18,93.395 42.886,93.395 43.547,94.056 44.656,94.056 44.975,94.375 44.975,94.85 45.411,95.286 U3.42@45.929,95.286
  Bottom Layer w0.2: R64.2@39.75,93.125 41.9,93.125 v1(42.175,93.4)
NetR69_1: R69.1 R70.2 R71.2 U10.39 | length 3.5
  Bottom Layer w0.3: U10.39@71.225,90.2 72.6,90.2 R71.2@72.7,90.1 R70.2@73.75,90.1 74.55,90.1 R69.1@74.675,89.975
NetR73_2: R73.2 U10.20 | length 1.5
  Bottom Layer w0.3: R73.2@61.275,89.2 U10.20@62.725,89.2
NetR74_1: R74.1 U10.44 | length 1.3
  Bottom Layer w0.3: U10.44@71.225,87.7 R74.1@72.575,87.7
NetR84_1: R84.1 U3.38 | length 22.1
  Top Layer w0.2: 44.327,96.431 44.782,96.886 U3.38@45.929,96.886
  Top Layer w0.5: 42.902,96.256 43.077,96.431 44.327,96.431
  Top Layer w0.6: 41.977,96.256 42.902,96.256
  Top Layer w1: v2(38.502,94.856) v2(38.502,95.706) v2(39.052,96.256) 41.977,96.256
  Signal Layer 4 w1: v2(39.052,96.256) v2(38.502,95.706) v2(38.502,94.856) 38.502,91.423 40.825,89.1 v2@40.825,88.625 ; v2(40.827,86.606) v2(40.827,87.581) v2(40.827,88.531)
  Bottom Layer w1: R84.1@40.827,85.981 v2(40.827,86.606) v2(40.827,87.581) v2(40.827,88.531)
NetR85_1: R85.1 U3.35 | length 24.8
  Top Layer w0.3: 44.675,99.025 U3.35@45.562,98.137
  Top Layer w0.5: v2@37.05,98.625 v2(37.45,99.025) 44.675,99.025
  Signal Layer 4 w0.6: v2@37.15,98.475 37.162,98.487 37.45,98.775 v2@37.45,99 ; 37.25,98.225 37.175,98.3 37.05,98.425 v2(37.05,98.6) v2@37.45,99 ; v2(37.45,99.025) v2@37.45,99
  Signal Layer 4 w0.8: v2@37.175,98.394 37.175,98.3 37.175,90.575 39.3,88.45 v2(39.3,87.15) v2(39.3,86.525)
  Bottom Layer w0.8: R85.1@39.3,85.85 v2(39.3,86.525) v2(39.3,87.15)
NetR88_1: R88.1 U10.2 | length 1.7
  Bottom Layer w0.2: U10.2@69.225,84.2 69.225,83.55 R88.1@69.975,82.8
NetR89_1: R89.1 U10.3 | length 1.5
  Bottom Layer w0.2: U10.3@68.725,84.2 68.725,83 R89.1@68.925,82.8
NetR98_1: R98.1 R99.1 U4.AA12 | length 2.9
  Top Layer w0.2: v1(24.61,61.6) U4.AA12@24.99,61.98
  Bottom Layer w0.2: R98.1@24.56,63.575 24.56,62.966 R99.1@25,62.525 24.61,62.135 v1(24.61,61.6)
NetR102_1: R102.1 U4.K22 | length 3.2
  Top Layer w0.12: v1(32.92,51.99) 32.92,52.67 33.34,53.09 33.34,53.53 U4.K22@33.79,53.98
  Bottom Layer w0.2: R102.1@32.68,51.21 32.68,51.75 v1(32.92,51.99)
NetSB1_1: SB1.1 SB3.2 U4.U2 | length 34.8
  Top Layer w0.09: v1(20.55,74.575) 20.925,74.575 21.35,75 22.983,75 24.768,73.215 25.71,73.215 27.885,71.04 27.885,70.653 28.19,70.348 U4.U2@28.19,69.98
  Top Layer w0.1: SB3.2@20.425,95.925 v1(21.3,95.925) 22.004,95.925 SB1.1@22.1,95.829
  Bottom Layer w0.1: v1(20.55,74.575) 20.55,75.05 19.875,75.725 19.875,82.75 20.775,83.65 20.775,84.875 21.9,86 21.9,92.15 21.3,92.75 v1(21.3,95.925)
NetSB2_2: SB2.2 SB4.1 U4.V2 | length 36.5
  Top Layer w0.09: 20.65,73.75 20.915,73.75 21.567,74.402 22.76,74.402 24.537,72.625 25.475,72.625 27.085,71.015 27.085,70.285 U4.V2@27.39,69.98
  Top Layer w0.1: 17.2,96 v1(18,96) 18.725,96 SB2.2@18.8,95.925 ; v1(18.625,74.825) 19,74.45 19.475,74.45 20.175,73.75 20.65,73.75
  Bottom Layer w0.1: v1(18,96) 18,93.425 18.45,92.975 18.45,83.285 17.225,82.06 17.225,79.397 16.4,78.572 16.4,77.05 v1(18.625,74.825)
NetTP3_1: TP3.1 U4.U1 | length 17.9
  Top Layer w0.1: TP3.1@14.45,78.825 v1(15.6,78.825) ; v1(20.05,74.95) 20.05,74.975 20.27,75.195 23.063,75.195 24.848,73.41 25.791,73.41 28.19,71.011 U4.U1@28.19,70.78
  Signal Layer 3 w0.1: v1(15.6,78.825) 15.6,78.081 17.181,76.5 18.5,76.5 v1(20.05,74.95)
NetTP12_1: TP12.1 U4.AA19 | length 5
  Top Layer w0.12: TP12.1@20.125,55.95 24.56,55.95 U4.AA19@24.99,56.38
NetTP16_1: TP16.1 U4.L22 | length 5
  Top Layer w0.12: TP16.1@31.83,49.9 31.83,50.59 32.04,50.8 32.4,50.8 32.723,51.123 32.723,51.467 32.45,51.74 32.45,52.78 32.99,53.32 U4.L22@32.99,53.98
